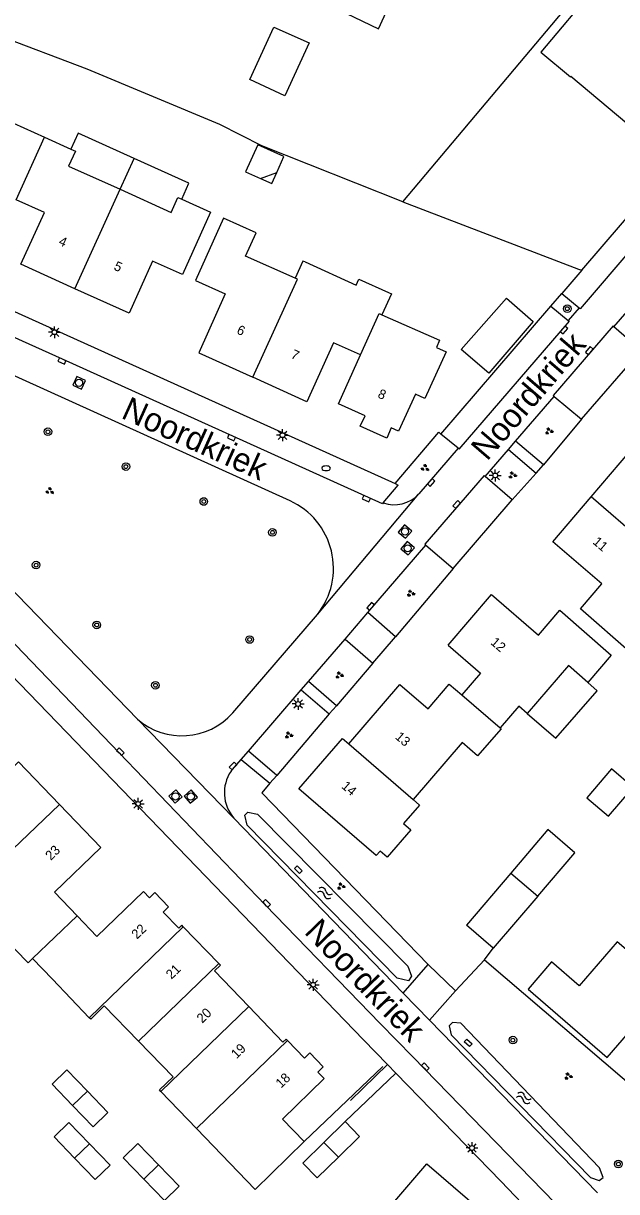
# Model space of a CAD drawing. Extents: x 136000 to 138005, y 398500 to 400500.
# Drawn here: x 137202.9 to 137265.3, y 398960.7 to 399083.5 of the extents above; entities that cross this region are included whole.
import ezdxf

# ---------------------------------------------------------------- set-up
doc = ezdxf.new("R2010")
doc.units = 0
for name, color, linetype in [('gg-afsc-erfafscheiding', 7, 'Continuous'), ('gg-afsc-hekwerk', 7, 'Continuous'), ('gg-afsc-muur', 7, 'Continuous'), ('gg-anno-huisnummerreeks BGT', 7, 'Continuous'), ('gg-anno-openbare ruimte label', 7, 'Continuous'), ('gg-bbg-bijgebouw', 7, 'Continuous'), ('gg-bbg-gedigitaliseerde bebouwing', 7, 'Continuous'), ('gg-bbg-gedigitaliseerde bijgebouw', 7, 'Continuous'), ('gg-bbg-hoofdgebouw', 7, 'Continuous'), ('gg-bbg-luifel en loopbrug', 7, 'Continuous'), ('gg-bbg-tussenscheiding', 7, 'Continuous'), ('gg-knt-verharding', 7, 'Continuous'), ('gg-knt-verharding nz', 7, 'Continuous'), ('gg-kntw-bovenkant insteek waterloop', 7, 'Continuous'), ('gt-grn-groengrens', 7, 'Continuous'), ('gt-grn-vlakafsluiter', 7, 'Continuous'), ('gt-grn-weggrens', 7, 'Continuous'), ('gt-symb-boom', 7, 'Continuous'), ('gt-symb-brandkraan', 7, 'Continuous'), ('gt-symb-groenvak', 7, 'Continuous'), ('gt-symb-kolk', 7, 'Continuous'), ('gt-symb-kolk center center', 7, 'Continuous'), ('gt-symb-lichtmast', 7, 'Continuous'), ('gt-symb-rioolschacht', 7, 'Continuous'), ('gt-symb-watersymbool', 7, 'Continuous')]:
    doc.layers.add(name, color=color, linetype=linetype)

# ---------------------------------------------------------------- blocks, each defined once
blk = doc.blocks.new('gt0-BOOM')
at = {"layer": 'gt-symb-boom'}
for radius in [0.4, 0.2]:
    blk.add_circle((0, 0), radius, dxfattribs=at)
blk = doc.blocks.new('gt0-GRVAK')
at = {"layer": 'gt-symb-groenvak'}
for p, q in [((-0.11, 0.19), (-0.23, 0.24)), ((-0.18, 0.15), (0.09, 0.15)), ((-0.09, 0.21), (-0.16, 0.32)), ((-0.05, 0.21), (-0.05, 0.39)), ((0, 0.21), (0.06, 0.32)), ((0.01, 0.19), (0.13, 0.24)), ((0.26, -0.05), (0.2, 0.06)), ((0.3, -0.05), (0.3, 0.13)), ((0.35, -0.05), (0.41, 0.06)), ((-0.24, -0.23), (-0.36, -0.18)), ((-0.32, -0.26), (-0.05, -0.26)), ((-0.23, -0.21), (-0.29, -0.1)), ((-0.18, -0.2), (-0.18, -0.02)), ((-0.14, -0.21), (-0.07, -0.1)), ((-0.12, -0.23), (0, -0.18)), ((0.24, -0.07), (0.12, -0.02)), ((0.17, -0.11), (0.44, -0.11)), ((0.37, -0.07), (0.49, -0.02))]:
    blk.add_line(p, q, dxfattribs=at)
blk = doc.blocks.new('gt0-LMAST')
at = {"layer": 'gt-symb-lichtmast'}
for p, q in [((-0.18, 0.17), (-0.45, 0.44)), ((-0.01, 0.25), (-0.01, 0.62)), ((0.17, 0.17), (0.44, 0.44)), ((-0.26, 0), (-0.63, 0)), ((-0.18, -0.18), (-0.45, -0.45)), ((-0.01, -0.25), (-0.01, -0.63)), ((0.44, -0.45), (0.17, -0.18)), ((0.24, 0), (0.62, 0))]:
    blk.add_line(p, q, dxfattribs=at)
blk.add_circle((-0.01, 0), 0.25, dxfattribs=at)
blk = doc.blocks.new('gt0-WA')
at = {"layer": 'gt-symb-watersymbool'}
for centre, start, end in [((-0.32, 0.02), 28.0725, 151.9275), ((0.43, 0.42), 208.0725, 331.9275), ((-0.32, -0.43), 28.0725, 151.9275), ((0.43, -0.03), 208.0725, 331.9275)]:
    blk.add_arc(centre, 0.425, start, end, dxfattribs=at)
blk = doc.blocks.new('gt0-KOLK')
at = {"layer": 'gt-symb-kolk'}
blk.add_lwpolyline([(0, 0), (0.37, 0), (0.37, 0.4), (-0.38, 0.4), (-0.38, 0), (0, 0)], dxfattribs=at)
blk = doc.blocks.new('gt0-KOLKCC')
at = {"layer": 'gt-symb-kolk center center'}
blk.add_lwpolyline([(-0.38, 0.2), (0.37, 0.2), (0.37, -0.2), (-0.38, -0.2)], close=True, dxfattribs=at)
blk = doc.blocks.new('gt0-RS')
at = {"layer": 'gt-symb-rioolschacht'}
blk.add_lwpolyline([(-0.5, -0.5), (0.5, -0.5), (0.5, 0.5), (-0.5, 0.5)], close=True, dxfattribs=at)
blk.add_circle((0, 0), 0.375, dxfattribs=at)
blk = doc.blocks.new('gt0-BR')
at = {"layer": 'gt-symb-brandkraan'}
for centre, radius, start, end in [((-0.24, 0), 0.206, 107.5669, 252.4331), ((0.6, -2.66), 3, 106.892, 107.5669), ((0, -0.69), 0.938, 73.108, 106.892), ((-0.6, -2.66), 3, 72.4331, 73.108), ((0.24, 0), 0.206, 287.567, 72.4331), ((0.6, 2.66), 3, 252.4331, 253.108), ((0, 0.69), 0.938, 253.108, 286.8921), ((-0.6, 2.66), 3, 286.8921, 287.567)]:
    blk.add_arc(centre, radius, start, end, dxfattribs=at)

msp = doc.modelspace()

# ---------------------------------------------------------------- linework, layer by layer
at = {"layer": 'gg-afsc-erfafscheiding'}
for p, q in [((137242.81, 399064.74), (137270, 399097)), ((137209.58, 399078.7), (137195.62, 399083.96)), ((137242.81, 399064.74), (137261.31, 399057.67)), ((137261.31, 399057.67), (137261.64, 399057.55)), ((137261.62, 399041.87), (137257.61, 399037.07)), ((137256.84, 399036.21), (137254.31, 399033.39)), ((137248.11, 399026.2), (137242.05, 399018.99)), ((137239.65, 399016.25), (137235.83, 399011.76)), ((137235.06, 399010.9), (137229.55, 399004.44)), ((137251.42, 398985.06), (137252.33, 398986.26)), ((137248.35, 398981.78), (137251.42, 398985.06)), ((137251.42, 398985.06), (137272.37, 398967.1)), ((137232.43, 398965.93), (137240.69, 398973.84))]:
    msp.add_line(p, q, dxfattribs=at)
for points in [[(137242.81, 399064.74), (137227.99, 399070.62), (137223.57, 399072.86)], [(137228.8, 399003.6), (137227.96, 399002.61), (137245.47, 398984.55)]]:
    msp.add_lwpolyline(points, dxfattribs=at)
at = {"layer": 'gg-afsc-hekwerk'}
for p, q in [((137261.64, 399057.55), (137271.1, 399068.56)), ((137242.09, 398973.14), (137236.73, 398968.03)), ((137253.15, 398961.73), (137242.09, 398973.14))]:
    msp.add_line(p, q, dxfattribs=at)
at = {"layer": 'gg-afsc-muur'}
msp.add_line((137223.57, 399072.86), (137209.58, 399078.7), dxfattribs=at)
at = {"layer": 'gg-bbg-bijgebouw'}
for p, q in [((137252.33, 398986.26), (137249.5, 398988.69)), ((137236.73, 398968.03), (137234.51, 398965.85))]:
    msp.add_line(p, q, dxfattribs=at)
for points in [[(137229.22, 399083.09), (137232.94, 399081.45), (137230.4, 399075.88), (137226.71, 399077.59), (137229.22, 399083.09)], [(137251.85, 399046.71), (137248.96, 399049.22), (137253.71, 399054.59), (137256.54, 399052.15), (137251.85, 399046.71)], [(137209.62, 398971.23), (137207.47, 398973.47), (137205.9, 398971.97), (137208.06, 398969.72)], [(137208.06, 398969.72), (137210.22, 398967.48), (137211.78, 398968.98), (137209.62, 398971.23)], [(137208.27, 398964.2), (137206.11, 398966.44), (137207.67, 398967.94), (137209.83, 398965.7)], [(137236.03, 398964.3), (137238.25, 398966.48), (137236.73, 398968.03)], [(137209.83, 398965.7), (137212, 398963.46), (137210.43, 398961.95), (137208.27, 398964.2)], [(137215.55, 398961.97), (137213.38, 398964.21), (137214.94, 398965.72), (137217.11, 398963.48)], [(137234.51, 398965.85), (137232.28, 398963.67), (137233.8, 398962.12), (137236.03, 398964.3)], [(137217.11, 398963.48), (137219.28, 398961.25), (137217.72, 398959.73), (137215.55, 398961.97)]]:
    msp.add_lwpolyline(points, dxfattribs=at)
at = {"layer": 'gg-bbg-gedigitaliseerde bebouwing'}
for p, q in [((137203.85, 398985.18), (137203.37, 398984.73)), ((137205.95, 398983), (137203.85, 398985.18)), ((137209.82, 398978.96), (137205.95, 398983)), ((137209.98, 398978.8), (137209.82, 398978.96))]:
    msp.add_line(p, q, dxfattribs=at)
at = {"layer": 'gg-bbg-gedigitaliseerde bijgebouw'}
for p, q in [((137227.82, 399067.18), (137229.54, 399067.83)), ((137254.16, 398994.15), (137249.5, 398988.69)), ((137257.01, 398991.72), (137252.33, 398986.26))]:
    msp.add_line(p, q, dxfattribs=at)
for points in [[(137229.54, 399067.83), (137230.29, 399069.51), (137227.56, 399070.74), (137226.27, 399067.88), (137227.82, 399067.18)], [(137262.17, 399002.08), (137264.45, 399000.13), (137267.05, 399003.17), (137264.76, 399005.12), (137262.17, 399002.08)], [(137257.01, 398991.72), (137260.92, 398996.3), (137258.07, 398998.73), (137254.16, 398994.15)]]:
    msp.add_lwpolyline(points, dxfattribs=at)
at = {"layer": 'gg-bbg-hoofdgebouw'}
for p, q in [((137201.85, 399073.01), (137205.12, 399071.52)), ((137205.12, 399071.52), (137207.89, 399070.27)), ((137255.01, 399011.7), (137253.05, 399009.43)), ((137255.9, 399010.93), (137255.01, 399011.7)), ((137208.54, 398989.66), (137210.61, 398987.5)), ((137223.46, 398984.64), (137219.71, 398988.51)), ((137221.09, 398967.32), (137217.34, 398971.21))]:
    msp.add_line(p, q, dxfattribs=at)
for points in [[(137235.12, 399085.37), (137240.24, 399082.91), (137242.85, 399088.61), (137245.84, 399087.21), (137248.73, 399093.56)], [(137268.41, 399087.91), (137265.96, 399085), (137263.13, 399087.36), (137257.34, 399080.46), (137260.45, 399077.87), (137260.5, 399077.93), (137266.38, 399073), (137268.58, 399075.63), (137269.33, 399075.01), (137271.52, 399077.6), (137272.96, 399076.37), (137275.87, 399079.86)], [(137207.89, 399070.27), (137208.35, 399070.06), (137207.63, 399068.5), (137213.06, 399066.05)], [(137213.06, 399066.05), (137218.43, 399063.62), (137219.14, 399065.2), (137219.54, 399065.02)], [(137208.31, 399055.6), (137202.62, 399058.17), (137205.1, 399063.63), (137202.14, 399064.96)], [(137219.54, 399065.02), (137222.57, 399063.65), (137219.61, 399057.08), (137216.48, 399058.49), (137214.01, 399053.03), (137208.31, 399055.6)], [(137231.49, 399056.7), (137226.27, 399059.03), (137227.38, 399061.47), (137223.95, 399063.02), (137220.98, 399056.46), (137224.12, 399055.05), (137221.34, 399048.86), (137227.03, 399046.29)], [(137232.54, 399058.41), (137232.3, 399058.51), (137231.49, 399056.7)], [(137232.54, 399058.41), (137237.9, 399055.99), (137238.17, 399056.6), (137241.3, 399055.19)], [(137241.3, 399055.19), (137241.61, 399055.05), (137240.6, 399052.86)], [(137240.6, 399052.86), (137246.68, 399050.2), (137246.35, 399049.42), (137247.37, 399048.97), (137245.14, 399044.06), (137244.14, 399044.52), (137242.37, 399040.62), (137241.6, 399040.97), (137241.12, 399039.9), (137238.33, 399041.15), (137238.85, 399042.22), (137236.03, 399043.51), (137238.35, 399048.64)], [(137238.35, 399048.64), (137235.52, 399049.91), (137232.72, 399043.72), (137227.03, 399046.29)], [(137262.64, 399033.73), (137266.69, 399038.47), (137271.85, 399034.03), (137273.95, 399036.48)], [(137271.18, 399026.32), (137267.32, 399021.85), (137269.34, 399020.1), (137266.87, 399017.25), (137261.51, 399021.96), (137263.74, 399024.57), (137258.58, 399028.99), (137262.64, 399033.73)], [(137247.57, 399018.13), (137252.14, 399023.44), (137257.08, 399019.19), (137259.33, 399021.8), (137264.74, 399017.09), (137262.28, 399014.21)], [(137247.57, 399018.13), (137250.98, 399015.19), (137249.01, 399012.91)], [(137262.28, 399014.21), (137260.26, 399015.97), (137255.9, 399010.93)], [(137237.13, 399007.74), (137242.51, 399013.98), (137245.46, 399011.44), (137247.7, 399014.04), (137249.01, 399012.91)], [(137253.05, 399009.43), (137253.15, 399009.33), (137250.66, 399006.48), (137249.06, 399007.89), (137243.91, 399001.9)], [(137243.91, 399001.9), (137244.57, 399001.31), (137242.88, 398999.36), (137243.66, 398998.71), (137241.17, 398995.82), (137240.41, 398996.48), (137239.99, 398996.01), (137231.88, 399003.01), (137236.45, 399008.32), (137237.13, 399007.74)], [(137195.21, 399003.45), (137197.45, 399001.13), (137202.36, 399005.86), (137206.7, 399001.36)], [(137206.7, 399001.36), (137211.03, 398996.86), (137206.15, 398992.15), (137208.54, 398989.66)], [(137203.37, 398984.73), (137200.75, 398987.43), (137201.23, 398987.9), (137196.96, 398992.26), (137198.38, 398993.66)], [(137219.71, 398988.51), (137219.56, 398988.67), (137219.25, 398988.38), (137217.59, 398990.07), (137218.15, 398990.6), (137216.72, 398992.11), (137216.15, 398991.57), (137215.52, 398992.24), (137210.61, 398987.5)], [(137267.26, 398985.31), (137265.36, 398986.95), (137261.35, 398982.32), (137258.47, 398984.82), (137256, 398981.96), (137264.3, 398974.78), (137266.55, 398977.38), (137271.69, 398972.94), (137275.91, 398977.81)], [(137226.59, 398980.14), (137222.98, 398983.87), (137223.62, 398984.48), (137223.46, 398984.64)], [(137215.01, 398976.48), (137211.4, 398980.19), (137209.98, 398978.8)], [(137230.66, 398976.55), (137230.52, 398976.71), (137230.2, 398976.4), (137226.59, 398980.14)], [(137217.34, 398971.21), (137217.2, 398971.36), (137218.64, 398972.75), (137215.01, 398976.48)], [(137230.66, 398976.55), (137232.45, 398974.71), (137233.01, 398975.26), (137234.43, 398973.79), (137233.86, 398973.24), (137234.53, 398972.55)], [(137234.53, 398972.55), (137230.14, 398968.3), (137232.43, 398965.93)], [(137221.09, 398967.32), (137227.26, 398960.91), (137232.43, 398965.93)], [(137241.76, 398959.44), (137245.35, 398963.61), (137255.42, 398954.93), (137251.92, 398950.85)]]:
    msp.add_lwpolyline(points, dxfattribs=at)
at = {"layer": 'gg-bbg-luifel en loopbrug'}
msp.add_line((137213.06, 399066.05), (137214.53, 399069.3), dxfattribs=at)
for points in [[(137214.53, 399069.3), (137208.65, 399071.96), (137207.89, 399070.27)], [(137219.54, 399065.02), (137220.29, 399066.7), (137214.53, 399069.3)], [(137227.82, 399067.18), (137229.01, 399066.65), (137229.54, 399067.83)], [(137255.9, 399010.93), (137258.9, 399008.34), (137263.27, 399013.34), (137262.28, 399014.21)]]:
    msp.add_lwpolyline(points, dxfattribs=at)
at = {"layer": 'gg-bbg-tussenscheiding'}
for p, q in [((137202.14, 399064.96), (137205.12, 399071.52)), ((137208.31, 399055.6), (137213.06, 399066.05)), ((137271.18, 399026.32), (137262.64, 399033.73)), ((137249.01, 399012.91), (137253.05, 399009.43)), ((137237.13, 399007.74), (137243.91, 399001.9)), ((137254.16, 398994.15), (137257.01, 398991.72)), ((137208.54, 398989.66), (137203.85, 398985.18)), ((137219.71, 398988.51), (137209.82, 398978.96)), ((137223.46, 398984.64), (137215.01, 398976.48)), ((137226.59, 398980.14), (137217.34, 398971.21)), ((137230.66, 398976.55), (137221.09, 398967.32)), ((137208.06, 398969.72), (137209.62, 398971.23)), ((137208.27, 398964.2), (137209.83, 398965.7)), ((137236.03, 398964.3), (137234.51, 398965.85)), ((137215.55, 398961.97), (137217.11, 398963.48))]:
    msp.add_line(p, q, dxfattribs=at)
for points in [[(137227.03, 399046.29), (137231.71, 399056.6), (137231.49, 399056.7)], [(137238.35, 399048.64), (137240.31, 399052.99), (137240.6, 399052.86)], [(137206.7, 399001.36), (137198.49, 398993.55), (137198.38, 398993.66)]]:
    msp.add_lwpolyline(points, dxfattribs=at)
at = {"layer": 'gg-knt-verharding'}
for p, q in [((137165.83, 399069.53), (137242, 399035.11)), ((137261.64, 399057.55), (137259.55, 399055.1)), ((137265.03, 399051.61), (137269.05, 399056.27)), ((137230.94, 399033.31), (137182.39, 399055.29)), ((137259.55, 399055.1), (137261.36, 399053.59)), ((137246.82, 399040.32), (137258.38, 399053.76)), ((137258.38, 399053.76), (137260.2, 399052.26)), ((137261.36, 399053.59), (137260.2, 399052.26)), ((137267.89, 399049.12), (137265.03, 399051.61)), ((137177.73, 399048.69), (137214.9, 399010.33)), ((137261.62, 399041.87), (137267.89, 399049.12)), ((137254.68, 399039.59), (137258.72, 399044.28)), ((137258.72, 399044.28), (137261.62, 399041.87)), ((137248.62, 399038.82), (137246.82, 399040.32)), ((137248.62, 399038.82), (137244.48, 399034.02)), ((137253.92, 399038.7), (137254.68, 399039.59)), ((137257.61, 399037.07), (137254.68, 399039.59)), ((137251.47, 399035.86), (137253.92, 399038.7)), ((137253.92, 399038.7), (137256.84, 399036.21)), ((137256.84, 399036.21), (137257.61, 399037.07)), ((137242, 399035.11), (137242.33, 399034.96)), ((137254.31, 399033.39), (137251.47, 399035.86)), ((137240.75, 399033.09), (137242.33, 399034.96)), ((137248.11, 399026.2), (137254.31, 399033.39)), ((137239.12, 399021.55), (137245.23, 399028.64)), ((137245.23, 399028.64), (137248.11, 399026.2)), ((137236.73, 399018.77), (137239.12, 399021.55)), ((137242.05, 399018.99), (137239.12, 399021.55)), ((137224.91, 399011.01), (137233.82, 399021.36)), ((137232.88, 399014.32), (137236.73, 399018.77)), ((137236.73, 399018.77), (137239.65, 399016.25)), ((137239.65, 399016.25), (137242.05, 399018.99)), ((137232.13, 399013.44), (137232.88, 399014.32)), ((137235.83, 399011.76), (137232.88, 399014.32)), ((137226.57, 399006.98), (137232.13, 399013.44)), ((137232.13, 399013.44), (137235.06, 399010.9)), ((137235.06, 399010.9), (137235.83, 399011.76)), ((137225.81, 399006.1), (137226.57, 399006.98)), ((137229.55, 399004.44), (137226.57, 399006.98)), ((137225.81, 399006.1), (137228.8, 399003.6)), ((137228.8, 399003.6), (137229.55, 399004.44)), ((137225.03, 398999.94), (137242.84, 398981.54)), ((137242.84, 398981.54), (137245.47, 398984.55)), ((137245.47, 398984.55), (137248.35, 398981.78)), ((137242.84, 398981.54), (137245.6, 398978.71)), ((137248.35, 398981.78), (137245.6, 398978.71)), ((137245.6, 398978.71), (137263.29, 398960.56)), ((137237.32, 398970.25), (137241.21, 398974.04)), ((137258.75, 398955.93), (137253.15, 398961.73))]:
    msp.add_line(p, q, dxfattribs=at)
for points in [[(137240.75, 399033.09), (137240.66, 399032.99), (137207.01, 399048.18), (137188.66, 399056.44), (137167.84, 399065.87), (137167.34, 399066.12)], [(137260.49, 398957.74), (137260.06, 398958.2), (137243.88, 398974.85), (137240.44, 398978.36), (137228.34, 398990.84), (137212.95, 399006.79), (137199.52, 399020.76), (137166.2, 399055.22), (137166.13, 399055.16)], [(137241.21, 398974.04), (137238.66, 398976.64), (137164.39, 399053.5)], [(137265.03, 399051.61), (137264.93, 399051.69), (137258.62, 399044.37), (137258.72, 399044.28)], [(137251.47, 399035.86), (137251.37, 399035.95), (137245.13, 399028.73), (137245.23, 399028.64)], [(137224.73, 399004.89), (137225.1, 399005.29), (137225.81, 399006.1)]]:
    msp.add_lwpolyline(points, dxfattribs=at)
for centre, radius, start, end in [((137241.93, 399036.32), 3.43, 249.9358, 317.9413), ((137227.71, 399026.2), 7.8, 321.61, 65.5533), ((137219.56, 399015.74), 7.14, 229.2015, 318.4783), ((137228.07, 399002.61), 4.04, 145.691, 221.2958)]:
    msp.add_arc(centre, radius, start, end, dxfattribs=at)
at = {"layer": 'gg-knt-verharding nz'}
for points in [[(137272.89, 399067.01), (137272.99, 399066.92), (137261.46, 399053.5), (137261.36, 399053.59)], [(137260.2, 399052.26), (137260.3, 399052.18), (137248.72, 399038.73), (137248.62, 399038.82)]]:
    msp.add_lwpolyline(points, dxfattribs=at)
at = {"layer": 'gg-kntw-bovenkant insteek waterloop'}
for points in [[(137226.42, 398999.19), (137226.18, 399000.24), (137226.51, 399000.58), (137227.51, 399000.34), (137243.35, 398984.36), (137243.72, 398983.34), (137243.39, 398982.84), (137242.2, 398983.1), (137226.42, 398999.19)], [(137248.93, 398978.38), (137248.03, 398978.44), (137247.68, 398978.11), (137247.89, 398977.17), (137262.55, 398962.15), (137263.46, 398961.84), (137263.88, 398962.16), (137263.49, 398963.17), (137248.93, 398978.38)]]:
    msp.add_lwpolyline(points, dxfattribs=at)
at = {"layer": 'gt-grn-groengrens'}
for p, q in [((137258.38, 399053.76), (137259.55, 399055.1)), ((137242, 399035.11), (137246.59, 399040.52)), ((137246.59, 399040.52), (137246.82, 399040.32))]:
    msp.add_line(p, q, dxfattribs=at)
at = {"layer": 'gt-grn-vlakafsluiter'}
msp.add_line((137241.21, 398974.04), (137242.09, 398973.14), dxfattribs=at)
at = {"layer": 'gt-grn-weggrens'}
for p, q in [((137233.82, 399021.36), (137244.48, 399034.02)), ((137214.9, 399010.33), (137225.03, 398999.94))]:
    msp.add_line(p, q, dxfattribs=at)

# ---------------------------------------------------------------- block references
at = {"layer": 'gt-symb-boom'}
for p in [(137260.12, 399053.5), (137205.47, 399040.56), (137213.67, 399036.9), (137221.87, 399033.23), (137229.09, 399029.98), (137204.22, 399026.54), (137210.6, 399020.25), (137226.69, 399018.72), (137216.78, 399013.91), (137254.39, 398976.6), (137265.49, 398963.57)]:
    msp.add_blockref('gt0-BOOM', p, dxfattribs=at)
at = {"layer": 'gt-symb-brandkraan'}
msp.add_blockref('gt0-BR', (137234.74, 399036.72), dxfattribs=at)
at = {"layer": 'gt-symb-groenvak'}
for p in [(137258.19, 399040.63), (137254.34, 399036), (137243.64, 399023.57), (137236.12, 399014.97), (137230.8, 399008.67), (137236.29, 398992.78), (137260.21, 398972.8)]:
    msp.add_blockref('gt0-GRVAK', p, dxfattribs=at)
at = {"layer": 'gt-symb-groenvak', "rotation": -20.864661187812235}
for p in [(137245.12, 399036.76), (137205.64, 399034.34)]:
    msp.add_blockref('gt0-GRVAK', p, dxfattribs=at)
at = {"layer": 'gt-symb-kolk'}
for p, rotation in [((137259.61, 399051.38), -129.40224128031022), ((137262.58, 399048.97), 49.013466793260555), ((137207.01, 399048.18), 155.66512570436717), ((137224.85, 399040.13), 155.66512570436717), ((137245.64, 399035.35), -130.7007448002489), ((137239.05, 399033.71), 155.92116276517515), ((137248.64, 399032.79), 48.770950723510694), ((137239.57, 399022.08), 49.21843280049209), ((137212.95, 399006.79), -46.13442163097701), ((137225.1, 399005.29), 46.74307034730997), ((137228.34, 398990.84), -45.891375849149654), ((137245.04, 398973.65), -45.81035302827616)]:
    msp.add_blockref('gt0-KOLK', p, dxfattribs=dict(at, rotation=rotation))
at = {"layer": 'gt-symb-kolk center center'}
for p, rotation in [((137231.82, 398994.53), 135.16208097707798), ((137249.68, 398976.32), 138.60919760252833)]:
    msp.add_blockref('gt0-KOLKCC', p, dxfattribs=dict(at, rotation=rotation))
at = {"layer": 'gt-symb-lichtmast'}
for p in [(137206.16, 399051.02), (137230.16, 399040.2), (137252.54, 399035.97), (137231.8, 399011.94), (137214.96, 399001.44), (137233.38, 398982.42), (137250.1, 398965.26)]:
    msp.add_blockref('gt0-LMAST', p, dxfattribs=at)
at = {"layer": 'gt-symb-rioolschacht'}
for p, rotation in [((137208.74, 399045.71), 155.10079947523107), ((137243.04, 399030.07), -130.94326214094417), ((137243.32, 399028.31), 49.98904228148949), ((137218.89, 399002.22), -47.876561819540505), ((137220.5, 399002.21), 130.90572608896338)]:
    msp.add_blockref('gt0-RS', p, dxfattribs=dict(at, rotation=rotation))
at = {"layer": 'gt-symb-watersymbool'}
for p, rotation in [((137234.58, 398992.08), -20.86466118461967), ((137255.49, 398970.55), -20.864661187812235)]:
    msp.add_blockref('gt0-WA', p, dxfattribs=dict(at, rotation=rotation))

# ---------------------------------------------------------------- texts
at = {"layer": 'gg-anno-huisnummerreeks BGT'}
for s, rotation, p in [('4', 335.7, (137206.51, 399060.25)), ('5', 335.7, (137212.32, 399057.63)), ('6', 335.7, (137225.25, 399050.92)), ('7', 335.7, (137230.95, 399048.35)), ('8', 335.9, (137240.09, 399044.2)), ('11', 319.5, (137262.72, 399028.87)), ('12', 319.3, (137251.97, 399018.3)), ('13', 319.2, (137241.93, 399008.37)), ('14', 319.3, (137236.28, 399003.18)), ('23', 44, (137205.77, 398995.44)), ('22', 43.5, (137214.83, 398987.16)), ('21', 44, (137218.46, 398982.94)), ('20', 44, (137221.7, 398978.32)), ('19', 44, (137225.31, 398974.59)), ('18', 44, (137230, 398971.5))]:
    msp.add_text(s, height=1, rotation=rotation, dxfattribs=at).set_placement(p)
at = {"layer": 'gg-anno-openbare ruimte label'}
for rotation, p in [(49.3, (137251.68, 399037.4)), (335.7, (137213.06, 399042.05)), (314, (137232.34, 398987.88))]:
    msp.add_text('Noordkriek', height=2.5, rotation=rotation, dxfattribs=at).set_placement(p)

doc.saveas('drawing.dxf')
